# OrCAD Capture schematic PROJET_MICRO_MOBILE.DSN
size B
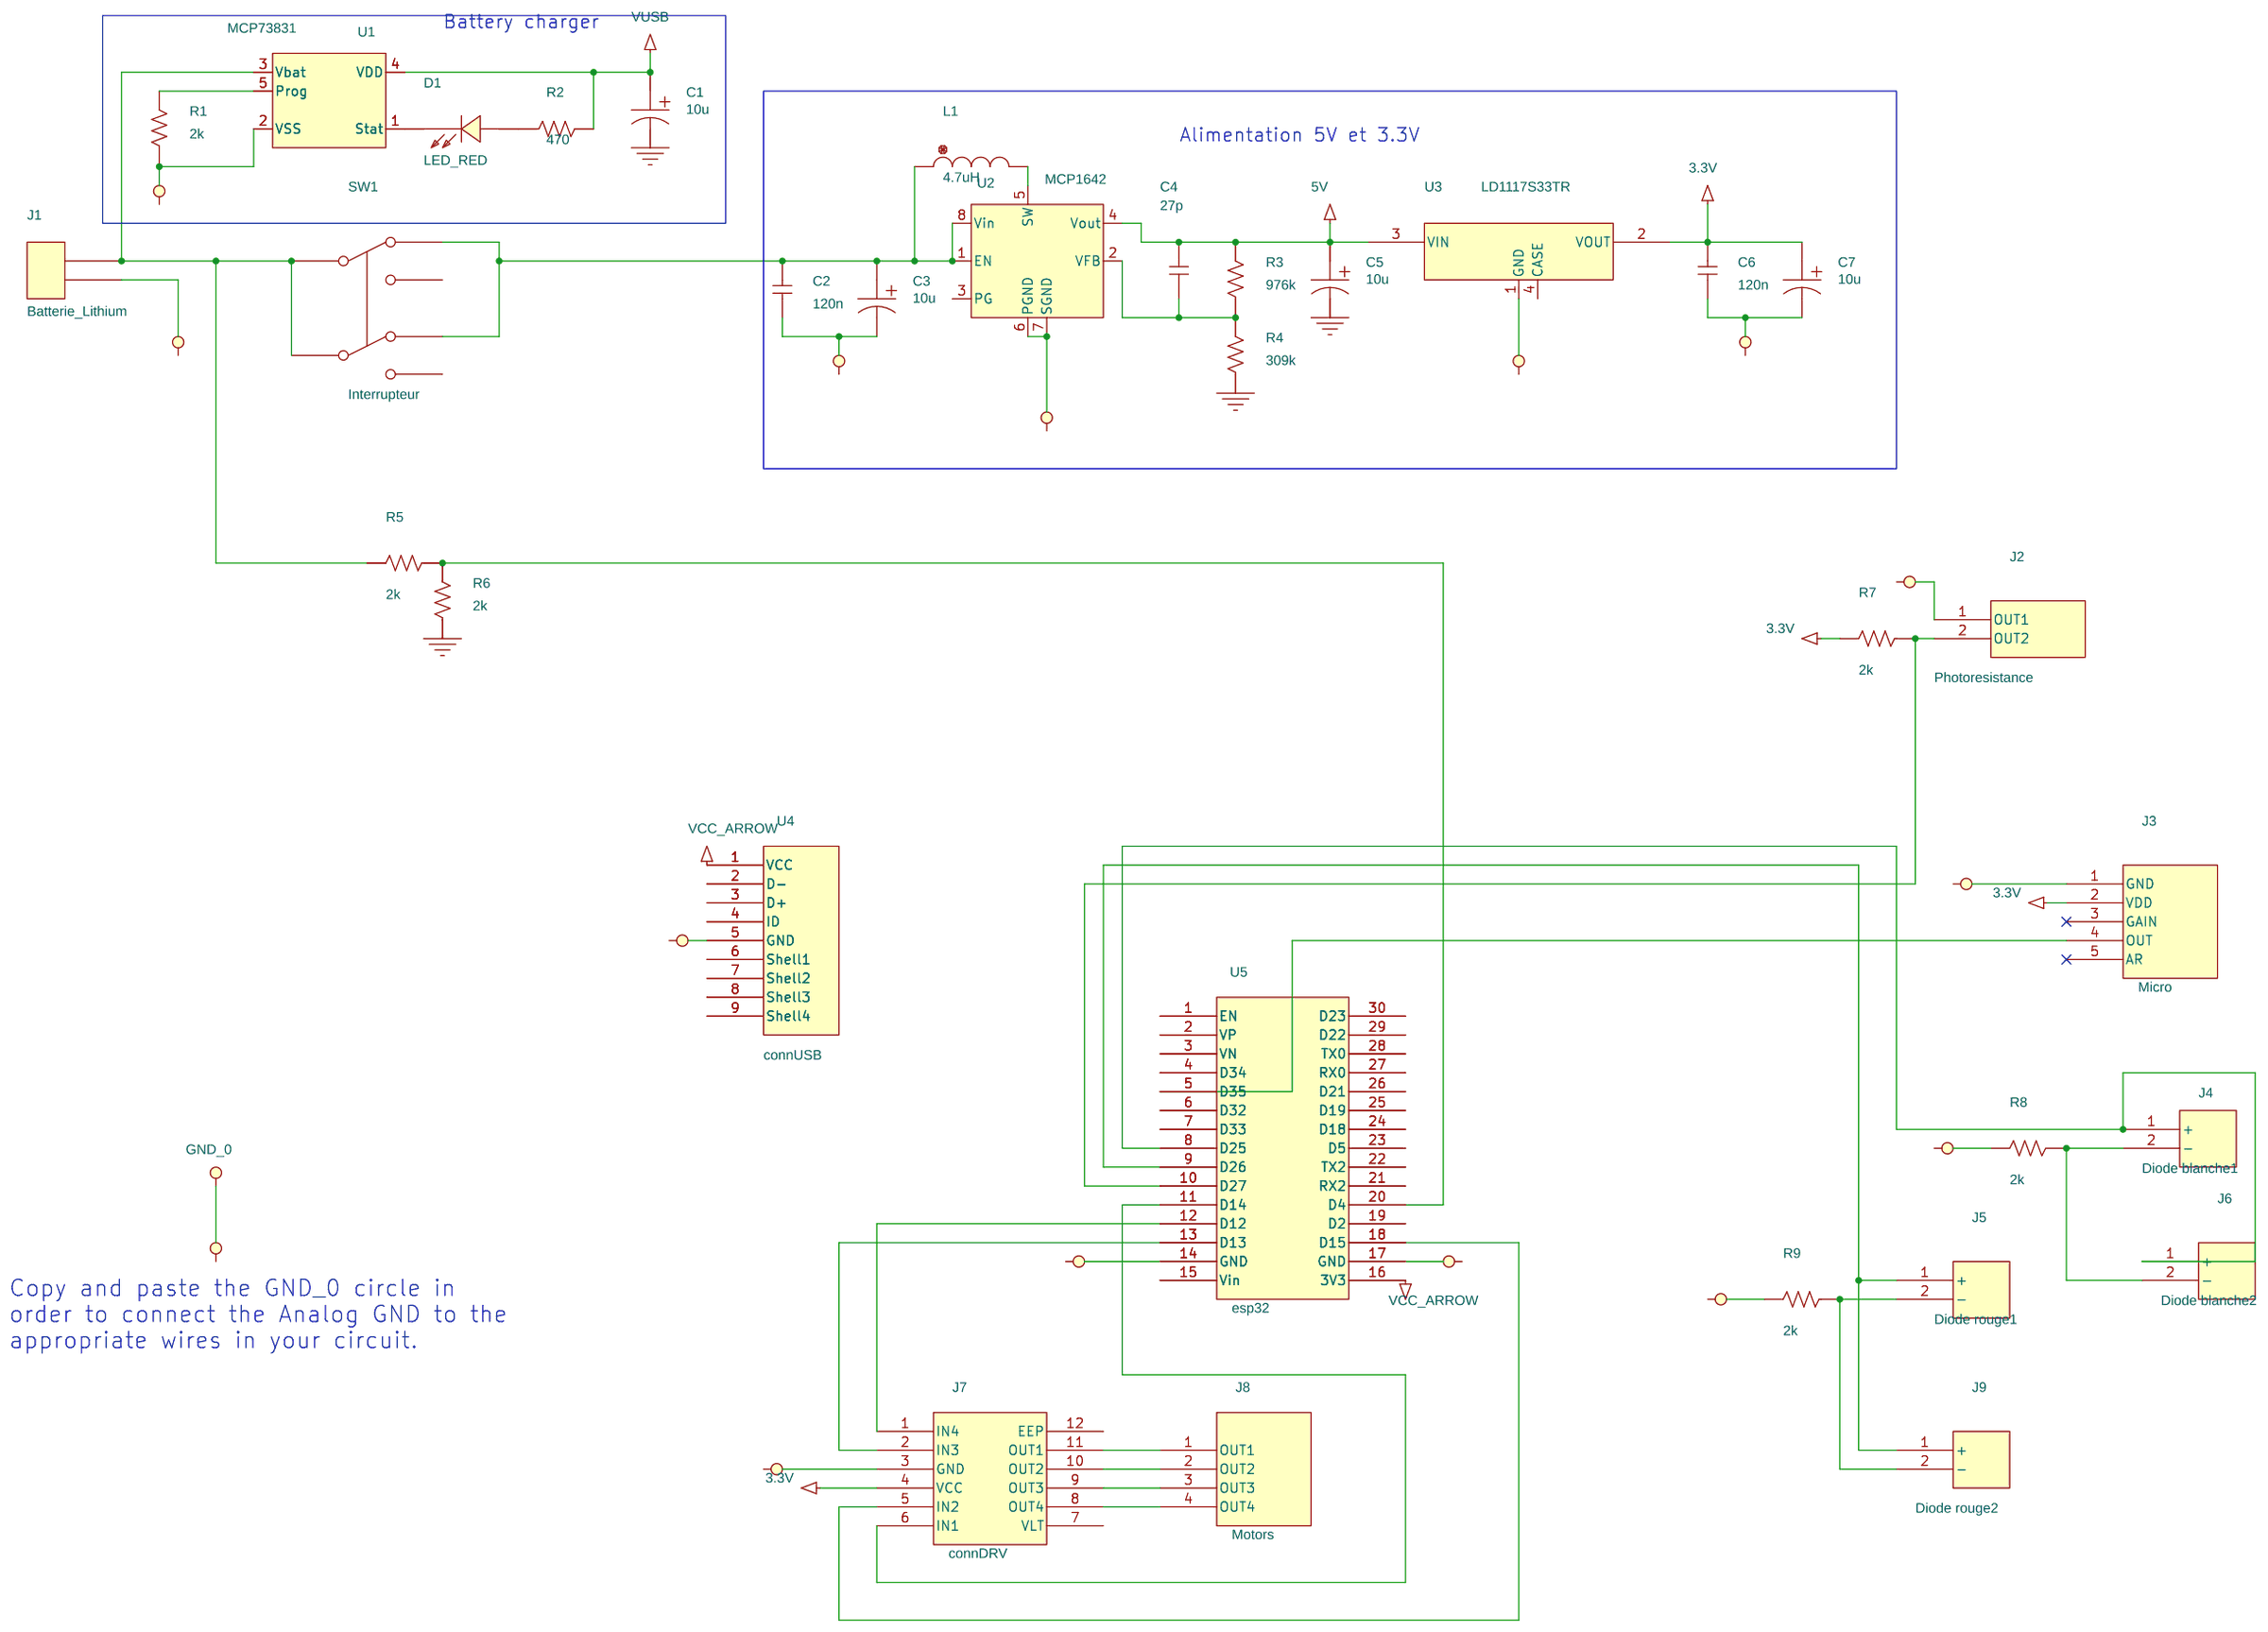
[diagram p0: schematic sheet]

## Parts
C1  10u  [smct1210]
C2  120n  [smc0805]
C3  10u  [smct1210]
C4  27p  [smc0805]
C5  10u  [smct1210]
C6  120n  [smc0805]
C7  10u  [smct1210]
D1  LED_RED  [SMD0805]
J1  Batterie_Lithium  [conalim]
J2  Photoresistance  [conn2_foot]
J3  Micro  [conn5_foot]
J4  Diode blanche1  [conn2_foot]
J5  Diode rouge1  [conn2_foot]
J6  Diode blanche2  [conn2_foot]
J7  connDRV  [DRV_foot]
J8  Motors  [conn4_foot]
J9  Diode rouge2  [conn2_foot]
L1  4.7uH  [sml1210]
R1  2k  [smr0805]
R2  470  [smr0805]
R3  976k  [smr0805]
R4  309k  [smr0805]
R5  2k  [smr0805]
R6  2k  [smr0805]
R7  2k  [smr0805]
R8  2k  [smr0805]
R9  2k  [smr0805]
SW1  Interrupteur  [interupteur]
U1  MCP73831  [5leadSOT23]
U2  MCP1642  [MSOP8]
U3  LD1117S33TR  [to261aasot223]
U4  connUSB  [conusb]
U5  esp32  [ESP_32]

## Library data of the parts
C1 C3 C5 C7 = CP
C2 C4 C6 = C
D1 = LED0805
J1 = CON2_0
J2 = conn2
J3 = conn5_0
J4-J6 J9 = conn2_1
J7 = connDRV
J8 = conn4
L1 = L
R1-R9 = R
SW1 = SW_KEY-Y1011_0
U1 = MCP73831
U2 = MCP1642_1
U3 = LD1117S33TR_0
U4 = connUSB_1
U5 = esp32

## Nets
3.3V: C6.2 C7.1 J3.2(VDD) J7.4(VCC) R7.2 U3.2(VOUT) U5.16(3V3)
5V: C4.2 C5.1 R3.2 U2.4(Vout) U3.3(VIN)
VIN: U5.15(Vin)
0: C1.2 C2.1 C3.2 C5.2 C6.1 C7.2 J1.- J2.1(OUT1) J3.1(GND) J7.3(GND) R1.1 R4.1 R6.1 R8.2 R9.2 U1.2(VSS) U2.6(PGND) U2.7(SGND) U3.1(GND) U4.5(GND) U5.14(GND) U5.17(GND)
CASE: U3.4(CASE)
VUSB: C1.1 R2.2 U1.4(VDD) U4.1(VCC)
N70085: J1.+ R5.2 SW1.2 SW1.5 U1.3(Vbat)
N70105: R1.2 U1.5(Prog)
N70321: C2.2 C3.1 L1.1 SW1.1 SW1.4 U2.1(EN) U2.8(Vin)
N74007: L1.2 U2.5(SW)
N74339: C4.1 R3.1 R4.2 U2.2(VFB)
N76144: J3.4(OUT) U5.5(D35)
N76694: J7.11(OUT1) J8.1(OUT1)
N76698: J7.10(OUT2) J8.2(OUT2)
N76711: J7.8(OUT4) J8.4(OUT4)
N76717: J7.9(OUT3) J8.3(OUT3)
N77907: J7.1(IN4) U5.12(D12)
N79860: J5.2(-) J9.2(-) R9.1
N80233: J4.2(-) J6.2(-) R8.1
N80351: J4.1(+) J6.1(+) U5.8(D25)
N80525: J5.1(+) J9.1(+) U5.9(D26)
N80737: J2.2(OUT2) R7.1 U5.10(D27)
N87816: J7.2(IN3) U5.13(D13)
N87824: J7.6(IN1) U5.11(D14)
N94189: R5.1 R6.2 U5.20(D4)
N98470: J7.5(IN2) U5.18(D15)
N101315: D1.C(CATHODE) U1.1(Stat)
N101318: D1.A(ANODE) R2.1

Not connected (* = marked no-connect by the designer): J3 3(GAIN)* 5(AR)*; J7 7(VLT) 12(EEP); SW1 3 6; U2 3(PG); U4 2(D-) 3(D+) 4(ID) 6(Shell1) 7(Shell2) 8(Shell3) 9(Shell4); U5 1(EN) 2(VP) 3(VN) 4(D34) 6(D32) 7(D33) 19(D2) 21(RX2) 22(TX2) 23(D5) 24(D18) 25(D19) 26(D21) 27(RX0) 28(TX0) 29(D22) 30(D23)

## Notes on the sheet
- Battery charger
- Alimentation 5V et 3.3V
- Copy and paste the GND_0 circle in
  order to connect the Analog GND to the
  appropriate wires in your circuit.
